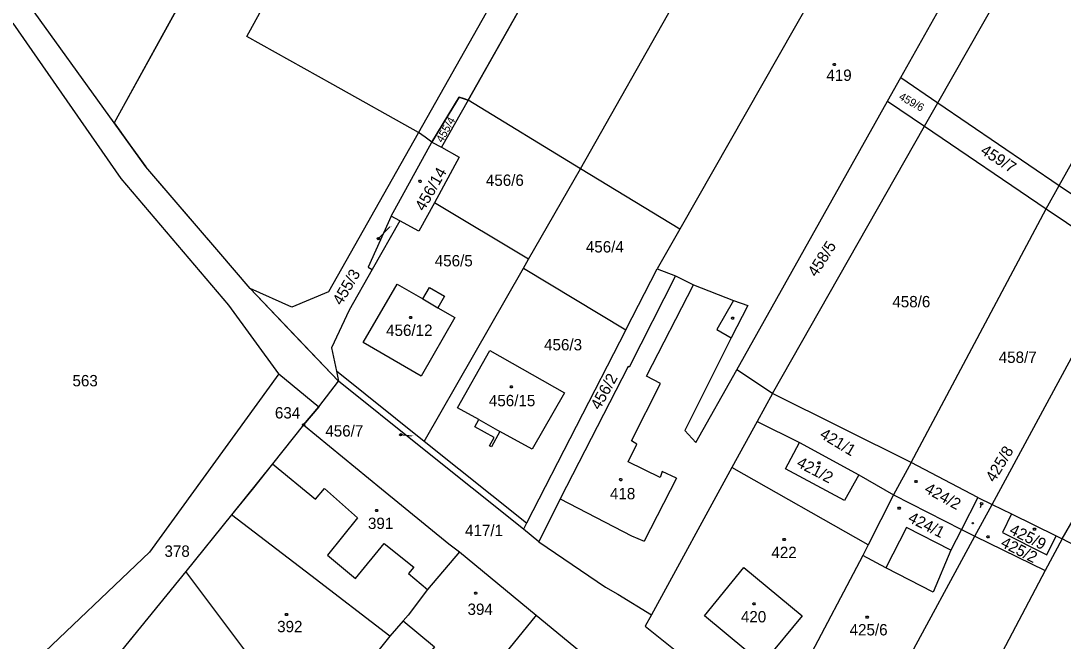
# Model space of a CAD drawing. Extents: x -634640 to -629202, y -1196156 to -1190068.
# Drawn here: x -631895.1 to -631739, y -1192341.9 to -1192249 of the extents above; entities that cross this region are included whole.
import ezdxf

# ---------------------------------------------------------------- set-up
doc = ezdxf.new("R2010")
doc.units = 0
for name, color, linetype in [('Obvod převzatý', 7, 'Continuous'), ('Obvod šetřený', 7, 'Continuous'), ('Vrstva 1', 7, 'Continuous'), ('Vrstva 2', 7, 'Continuous'), ('Vrstva 3', 7, 'Continuous'), ('Vrstva 4', 7, 'Continuous'), ('Vrstva 5', 7, 'Continuous'), ('Vrstva 7', 7, 'Continuous'), ('Vrstva 8', 7, 'Continuous')]:
    doc.layers.add(name, color=color, linetype=linetype)

msp = doc.modelspace()

# ---------------------------------------------------------------- linework, layer by layer
at = {"layer": 'Obvod převzatý'}
for points in [[(-631828.14, -1192260.86), (-631828.805, -1192260.62), (-631829.47, -1192260.38), (-631831.52, -1192263.755), (-631833.57, -1192267.13), (-631834.565, -1192266.415), (-631835.56, -1192265.7), (-631848.41, -1192258.505), (-631861.26, -1192251.31), (-631858.765, -1192246.78), (-631856.27, -1192242.25), (-631860.915, -1192239.685), (-631866.088, -1192236.828), (-631873.777, -1192250.837), (-631881.15, -1192264.27), (-631878.79, -1192267.545), (-631876.43, -1192270.82)], [(-631847.57, -1192302.96), (-631854.17, -1192296.005), (-631860.77, -1192289.05), (-631865.5, -1192283.55), (-631870.965, -1192277.185), (-631876.43, -1192270.82)], [(-631852.78, -1192309.47), (-631850.5, -1192306.81), (-631847.57, -1192302.96)], [(-631852.78, -1192309.47), (-631857.43, -1192315.35), (-631860.495, -1192319.155), (-631863.56, -1192322.96), (-631870.4, -1192331.45), (-631881.165, -1192344.625), (-631891.93, -1192357.8)]]:
    msp.add_lwpolyline(points, dxfattribs=at)
at = {"layer": 'Obvod šetřený'}
msp.add_lwpolyline([(-631828.14, -1192260.86), (-631770.72, -1192159.345), (-631713.3, -1192057.83), (-631710.55, -1192057.545), (-631707.8, -1192057.26), (-631694.81, -1192065.06), (-631675.8, -1192076.49), (-631658.57, -1192086.85), (-631641.27, -1192097.24), (-631633.835, -1192101.715), (-631626.4, -1192106.19), (-631621.345, -1192109.22), (-631616.29, -1192112.25), (-631611.64, -1192115.048), (-631606.99, -1192117.845), (-631603.89, -1192119.71), (-631598.89, -1192123.93), (-631590.975, -1192122.16)], dxfattribs=at)
at = {"layer": 'Vrstva 1'}
for p, q in [((-631713.3, -1192057.83), (-631828.14, -1192260.86)), ((-631811.29, -1192271.13), (-631694.81, -1192065.06)), ((-631757.75, -1192261.26), (-631658.57, -1192086.85)), ((-631881.15, -1192264.27), (-631944.14, -1192176.84)), ((-631787.54, -1192180.78), (-631849.06, -1192289.57)), ((-631739.56, -1192273.61), (-631693.54, -1192191.04)), ((-631763.12, -1192221.67), (-631796.42, -1192280.19)), ((-631763.31, -1192257.48), (-631746.9, -1192228.25)), ((-631866.403, -1192237.404), (-631881.15, -1192264.27)), ((-631880.13, -1192272.61), (-631896.29, -1192249.34)), ((-631765.27, -1192260.98), (-631763.31, -1192257.48)), ((-631763.31, -1192257.48), (-631757.75, -1192261.26)), ((-631833.57, -1192267.13), (-631829.47, -1192260.38)), ((-631828.14, -1192260.86), (-631832.13, -1192267.91)), ((-631829.47, -1192260.38), (-631828.14, -1192260.86)), ((-631811.29, -1192271.13), (-631828.14, -1192260.86)), ((-631787.88, -1192301.25), (-631765.27, -1192260.98)), ((-631765.27, -1192260.98), (-631759.73, -1192264.74)), ((-631759.73, -1192264.74), (-631757.75, -1192261.26)), ((-631757.75, -1192261.26), (-631739.56, -1192273.61)), ((-631876.43, -1192270.82), (-631881.15, -1192264.27)), ((-631782.51, -1192304.79), (-631759.73, -1192264.74)), ((-631759.73, -1192264.74), (-631741.52, -1192277.11)), ((-631839.63, -1192278.23), (-631833.57, -1192267.13)), ((-631833.57, -1192267.13), (-631832.13, -1192267.91)), ((-631829.45, -1192269.37), (-631833.18, -1192276.23)), ((-631832.13, -1192267.91), (-631829.45, -1192269.37)), ((-631865.5, -1192283.55), (-631876.43, -1192270.82)), ((-631819.08, -1192284.69), (-631811.29, -1192271.13)), ((-631796.42, -1192280.19), (-631811.29, -1192271.13)), ((-631863.97, -1192291.54), (-631880.13, -1192272.61)), ((-631741.52, -1192277.11), (-631739.56, -1192273.61)), ((-631739.56, -1192273.61), (-631728, -1192281.47)), ((-631833.18, -1192276.23), (-631835.51, -1192280.5)), ((-631819.08, -1192284.69), (-631833.18, -1192276.23)), ((-631761.74, -1192315.12), (-631741.52, -1192277.11)), ((-631741.52, -1192277.11), (-631729.91, -1192285)), ((-631839.63, -1192278.23), (-631843.1, -1192285.89)), ((-631838.36, -1192278.93), (-631839.63, -1192278.23)), ((-631838.36, -1192278.93), (-631842.5, -1192286.24)), ((-631835.51, -1192280.5), (-631838.36, -1192278.93)), ((-631796.42, -1192280.19), (-631799.78, -1192286.1)), ((-631860.77, -1192289.05), (-631865.5, -1192283.55)), ((-631819.85, -1192286.04), (-631819.08, -1192284.69)), ((-631749.63, -1192321.4), (-631729.91, -1192285)), ((-631842.5, -1192286.24), (-631845.93, -1192292.3)), ((-631843.1, -1192285.89), (-631842.5, -1192286.24)), ((-631834.72, -1192311.97), (-631819.85, -1192286.04)), ((-631819.85, -1192286.04), (-631804.48, -1192295.24)), ((-631804.48, -1192295.24), (-631799.78, -1192286.1)), ((-631799.78, -1192286.1), (-631797.04, -1192287.17)), ((-631797.04, -1192287.17), (-631803.97, -1192300.84)), ((-631797.04, -1192287.17), (-631794.35, -1192288.51)), ((-631854.54, -1192291.88), (-631860.77, -1192289.05)), ((-631847.57, -1192302.96), (-631860.77, -1192289.05)), ((-631849.06, -1192289.57), (-631854.54, -1192291.88)), ((-631843.86, -1192297.16), (-631838.77, -1192288.4)), ((-631838.77, -1192288.4), (-631834.91, -1192290.62)), ((-631834.91, -1192290.62), (-631833.93, -1192288.9)), ((-631833.93, -1192288.9), (-631831.65, -1192290.21)), ((-631794.35, -1192288.51), (-631788.38, -1192290.84)), ((-631831.65, -1192290.21), (-631832.66, -1192291.96)), ((-631788.38, -1192290.84), (-631786.21, -1192291.59)), ((-631856.48, -1192301.87), (-631863.97, -1192291.54)), ((-631845.93, -1192292.3), (-631848.57, -1192297.95)), ((-631832.66, -1192291.96), (-631830.1, -1192293.43)), ((-631786.21, -1192291.59), (-631788.73, -1192296.44)), ((-631739.13, -1192326.55), (-631719.28, -1192292.22)), ((-631830.1, -1192293.43), (-631835.15, -1192302.2)), ((-631804.48, -1192295.24), (-631819.39, -1192324.23)), ((-631835.15, -1192302.2), (-631843.86, -1192297.16)), ((-631788.73, -1192296.44), (-631795.67, -1192310.34)), ((-631848.57, -1192297.95), (-631847.87, -1192301.46)), ((-631829.73, -1192306.93), (-631824.87, -1192298.35)), ((-631824.87, -1192298.35), (-631813.68, -1192304.69)), ((-631856.48, -1192301.87), (-631875.84, -1192328.57)), ((-631856.48, -1192301.87), (-631850.5, -1192306.81)), ((-631834.72, -1192311.97), (-631847.87, -1192301.46)), ((-631847.87, -1192301.46), (-631847.57, -1192302.96)), ((-631804.15, -1192300.77), (-631814.31, -1192320.55)), ((-631803.97, -1192300.84), (-631804.15, -1192300.77)), ((-631793.99, -1192312.11), (-631787.88, -1192301.25)), ((-631782.51, -1192304.79), (-631787.88, -1192301.25)), ((-631835.22, -1192312.84), (-631847.57, -1192302.96)), ((-631813.68, -1192304.69), (-631818.55, -1192313.15)), ((-631782.51, -1192304.79), (-631784.81, -1192308.99)), ((-631761.74, -1192315.12), (-631782.51, -1192304.79)), ((-631850.5, -1192306.81), (-631852.78, -1192309.47)), ((-631826.53, -1192308.68), (-631829.73, -1192306.93)), ((-631852.78, -1192309.47), (-631857.43, -1192315.35)), ((-631852.78, -1192309.47), (-631841.11, -1192319.08)), ((-631827.12, -1192309.77), (-631826.53, -1192308.68)), ((-631824.22, -1192311.36), (-631827.12, -1192309.77)), ((-631784.81, -1192308.99), (-631788.59, -1192315.9)), ((-631784.81, -1192308.99), (-631778.45, -1192312.11)), ((-631824.92, -1192312.63), (-631824.22, -1192311.36)), ((-631823.38, -1192310.5), (-631824.63, -1192312.79)), ((-631818.55, -1192313.15), (-631823.38, -1192310.5)), ((-631795.67, -1192310.34), (-631793.99, -1192312.11)), ((-631819.85, -1192325.12), (-631835.22, -1192312.84)), ((-631819.39, -1192324.23), (-631834.72, -1192311.97)), ((-631824.63, -1192312.79), (-631824.92, -1192312.63)), ((-631778.45, -1192312.11), (-631769.57, -1192316.97)), ((-631857.43, -1192315.35), (-631863.56, -1192322.96)), ((-631788.59, -1192315.9), (-631800.66, -1192337.95)), ((-631768.17, -1192327.46), (-631788.59, -1192315.9)), ((-631761.74, -1192315.12), (-631764.41, -1192319.96)), ((-631751.74, -1192320.37), (-631761.74, -1192315.12)), ((-631769.57, -1192316.97), (-631764.41, -1192319.96)), ((-631841.11, -1192319.08), (-631831.02, -1192327.29)), ((-631814.31, -1192320.55), (-631817.51, -1192326.99)), ((-631764.41, -1192319.96), (-631768.17, -1192327.46)), ((-631764.41, -1192319.96), (-631754.22, -1192325.15)), ((-631751.74, -1192320.37), (-631754.22, -1192325.15)), ((-631751.74, -1192320.37), (-631749.63, -1192321.4)), ((-631752.2, -1192326.14), (-631749.63, -1192321.4)), ((-631749.63, -1192321.4), (-631746.69, -1192322.84)), ((-631863.56, -1192322.96), (-631870.4, -1192331.45)), ((-631851.67, -1192332.08), (-631863.56, -1192322.96)), ((-631746.69, -1192322.84), (-631748.08, -1192325.63)), ((-631746.69, -1192322.84), (-631740.03, -1192326.11)), ((-631819.39, -1192324.23), (-631819.85, -1192325.12)), ((-631817.51, -1192326.99), (-631819.85, -1192325.12)), ((-631754.22, -1192325.15), (-631755.82, -1192328.27)), ((-631754.22, -1192325.15), (-631752.2, -1192326.14)), ((-631817.51, -1192326.99), (-631807.54, -1192333.79)), ((-631764.26, -1192348.42), (-631752.2, -1192326.14)), ((-631752.2, -1192326.14), (-631741.66, -1192331.32)), ((-631748.08, -1192325.63), (-631741.44, -1192328.95)), ((-631739.13, -1192326.55), (-631741.66, -1192331.32)), ((-631741.44, -1192328.95), (-631740.03, -1192326.11)), ((-631740.03, -1192326.11), (-631739.13, -1192326.55)), ((-631721.73, -1192335.89), (-631739.13, -1192326.55)), ((-631875.84, -1192328.57), (-631900.25, -1192351.76)), ((-631829.42, -1192328.51), (-631834.19, -1192334.13)), ((-631831.02, -1192327.29), (-631829.42, -1192328.51)), ((-631829.42, -1192328.51), (-631817.92, -1192338.02)), ((-631768.17, -1192327.46), (-631768.96, -1192329.04)), ((-631755.82, -1192328.27), (-631758.45, -1192334.54)), ((-631768.96, -1192329.04), (-631781.21, -1192352.21)), ((-631765.52, -1192330.91), (-631768.96, -1192329.04)), ((-631870.4, -1192331.45), (-631891.93, -1192357.8)), ((-631851.91, -1192356.15), (-631870.4, -1192331.45)), ((-631792.72, -1192338.1), (-631786.79, -1192330.85)), ((-631786.79, -1192330.85), (-631778.05, -1192338.09)), ((-631758.45, -1192334.54), (-631765.52, -1192330.91)), ((-631741.66, -1192331.32), (-631755.6, -1192357.68)), ((-631839.86, -1192341.15), (-631851.67, -1192332.08)), ((-631834.19, -1192334.13), (-631837.09, -1192337.98)), ((-631807.54, -1192333.79), (-631805.69, -1192334.85)), ((-631805.69, -1192334.85), (-631800.66, -1192337.95)), ((-631837.09, -1192337.98), (-631837.84, -1192338.84)), ((-631817.92, -1192338.02), (-631825.64, -1192347.45)), ((-631817.92, -1192338.02), (-631805.35, -1192348.31)), ((-631800.66, -1192337.95), (-631801.6, -1192339.67)), ((-631786.5, -1192343.23), (-631792.72, -1192338.1)), ((-631778.05, -1192338.09), (-631783.6, -1192344.79)), ((-631837.84, -1192338.84), (-631839.86, -1192341.15)), ((-631801.6, -1192339.67), (-631782.54, -1192354.73)), ((-631839.86, -1192341.15), (-631845.68, -1192348.4))]:
    msp.add_line(p, q, dxfattribs=at)
at = {"layer": 'Vrstva 3'}
for points in [[(-631773.18, -1192255.37), (-631773.09, -1192255.52), (-631773.18, -1192255.67), (-631773.36, -1192255.67), (-631773.45, -1192255.52), (-631773.36, -1192255.37), (-631773.18, -1192255.37)], [(-631752.44, -1192324.1), (-631752.379, -1192324.2), (-631752.44, -1192324.3), (-631752.56, -1192324.3), (-631752.621, -1192324.2), (-631752.56, -1192324.1), (-631752.44, -1192324.1)], [(-631780.68, -1192326.49), (-631780.59, -1192326.64), (-631780.68, -1192326.79), (-631780.86, -1192326.79), (-631780.95, -1192326.64), (-631780.86, -1192326.49), (-631780.68, -1192326.49)], [(-631750.16, -1192326.1), (-631750.07, -1192326.25), (-631750.16, -1192326.4), (-631750.34, -1192326.4), (-631750.43, -1192326.25), (-631750.34, -1192326.1), (-631750.16, -1192326.1)], [(-631855.25, -1192337.74), (-631855.16, -1192337.89), (-631855.25, -1192338.04), (-631855.43, -1192338.04), (-631855.52, -1192337.89), (-631855.43, -1192337.74), (-631855.25, -1192337.74)], [(-631768.24, -1192338.16), (-631768.15, -1192338.31), (-631768.24, -1192338.46), (-631768.42, -1192338.46), (-631768.51, -1192338.31), (-631768.42, -1192338.16), (-631768.24, -1192338.16)]]:
    msp.add_lwpolyline(points, dxfattribs=at)
at = {"layer": 'Vrstva 4'}
for p, q in [((-631801.42, -1192302.18), (-631794.35, -1192288.51)), ((-631834.91, -1192290.62), (-631832.66, -1192291.96)), ((-631788.38, -1192290.84), (-631790.87, -1192295.22)), ((-631790.87, -1192295.22), (-631788.73, -1192296.44)), ((-631799.31, -1192303.27), (-631801.42, -1192302.18)), ((-631803.66, -1192311.89), (-631799.31, -1192303.27)), ((-631826.53, -1192308.68), (-631823.38, -1192310.5)), ((-631804.15, -1192315.02), (-631802.84, -1192312.39)), ((-631802.84, -1192312.39), (-631803.66, -1192311.89)), ((-631780.57, -1192316.1), (-631778.45, -1192312.11)), ((-631857.43, -1192315.35), (-631850.99, -1192320.63)), ((-631799.37, -1192317.37), (-631804.15, -1192315.02)), ((-631771.72, -1192320.82), (-631780.57, -1192316.1)), ((-631796.89, -1192317.48), (-631801.73, -1192326.93)), ((-631799.06, -1192316.47), (-631799.37, -1192317.37)), ((-631796.89, -1192317.48), (-631799.06, -1192316.47)), ((-631769.57, -1192316.97), (-631771.72, -1192320.82)), ((-631850.99, -1192320.63), (-631849.66, -1192319.04)), ((-631849.66, -1192319.04), (-631844.69, -1192323.41)), ((-631814.31, -1192320.55), (-631803.63, -1192326.1)), ((-631844.69, -1192323.41), (-631849.21, -1192329.03)), ((-631762.44, -1192324.89), (-631765.52, -1192330.91)), ((-631755.82, -1192328.27), (-631762.44, -1192324.89)), ((-631803.63, -1192326.1), (-631801.73, -1192326.93)), ((-631845.01, -1192332.52), (-631840.7, -1192327.26)), ((-631840.7, -1192327.26), (-631836.25, -1192330.8)), ((-631849.21, -1192329.03), (-631845.01, -1192332.52)), ((-631836.25, -1192330.8), (-631837.07, -1192331.76)), ((-631837.07, -1192331.76), (-631834.19, -1192334.13))]:
    msp.add_line(p, q, dxfattribs=at)
msp.add_lwpolyline([(-631837.84, -1192338.84), (-631833.18, -1192342.75), (-631833.85, -1192343.6), (-631830.54, -1192346.35), (-631829.8, -1192345.43), (-631826.35, -1192348.31)], dxfattribs=at)
at = {"layer": 'Vrstva 5'}
for points in [[(-631835.23, -1192272.86), (-631835.14, -1192273.01), (-631835.23, -1192273.16), (-631835.41, -1192273.16), (-631835.5, -1192273.01), (-631835.41, -1192272.86), (-631835.23, -1192272.86)], [(-631836.64, -1192293.26), (-631836.55, -1192293.41), (-631836.64, -1192293.56), (-631836.82, -1192293.56), (-631836.91, -1192293.41), (-631836.82, -1192293.26), (-631836.64, -1192293.26)], [(-631788.41, -1192293.36), (-631788.32, -1192293.51), (-631788.41, -1192293.66), (-631788.59, -1192293.66), (-631788.68, -1192293.51), (-631788.59, -1192293.36), (-631788.41, -1192293.36)], [(-631821.55, -1192303.64), (-631821.46, -1192303.79), (-631821.55, -1192303.94), (-631821.73, -1192303.94), (-631821.82, -1192303.79), (-631821.73, -1192303.64), (-631821.55, -1192303.64)], [(-631775.48, -1192315.04), (-631775.39, -1192315.19), (-631775.48, -1192315.34), (-631775.66, -1192315.34), (-631775.75, -1192315.19), (-631775.66, -1192315.04), (-631775.48, -1192315.04)], [(-631805.16, -1192317.55), (-631805.07, -1192317.7), (-631805.16, -1192317.85), (-631805.34, -1192317.85), (-631805.43, -1192317.7), (-631805.34, -1192317.55), (-631805.16, -1192317.55)], [(-631760.93, -1192317.81), (-631760.84, -1192317.96), (-631760.93, -1192318.11), (-631761.11, -1192318.11), (-631761.2, -1192317.96), (-631761.11, -1192317.81), (-631760.93, -1192317.81)], [(-631841.73, -1192322.19), (-631841.64, -1192322.34), (-631841.73, -1192322.49), (-631841.91, -1192322.49), (-631842, -1192322.34), (-631841.91, -1192322.19), (-631841.73, -1192322.19)], [(-631763.45, -1192321.81), (-631763.36, -1192321.96), (-631763.45, -1192322.11), (-631763.63, -1192322.11), (-631763.72, -1192321.96), (-631763.63, -1192321.81), (-631763.45, -1192321.81)], [(-631743.17, -1192324.96), (-631743.08, -1192325.11), (-631743.17, -1192325.26), (-631743.35, -1192325.26), (-631743.44, -1192325.11), (-631743.35, -1192324.96), (-631743.17, -1192324.96)], [(-631826.89, -1192334.57), (-631826.8, -1192334.72), (-631826.89, -1192334.87), (-631827.07, -1192334.87), (-631827.16, -1192334.72), (-631827.07, -1192334.57), (-631826.89, -1192334.57)], [(-631785.22, -1192336.17), (-631785.13, -1192336.32), (-631785.22, -1192336.47), (-631785.4, -1192336.47), (-631785.49, -1192336.32), (-631785.4, -1192336.17), (-631785.22, -1192336.17)]]:
    msp.add_lwpolyline(points, dxfattribs=at)
at = {"layer": 'Vrstva 7'}
for p, q in [((-631839.85, -1192279.83), (-631841.58, -1192281.6)), ((-631836.59, -1192311.16), (-631838.24, -1192310.97)), ((-631751.36, -1192321.85), (-631751.2, -1192321.3))]:
    msp.add_line(p, q, dxfattribs=at)
for points in [[(-631841.749, -1192281.644), (-631841.709, -1192281.474), (-631841.539, -1192281.43), (-631841.411, -1192281.556), (-631841.451, -1192281.726), (-631841.621, -1192281.77), (-631841.749, -1192281.644)], [(-631838.379, -1192310.864), (-631838.22, -1192310.791), (-631838.081, -1192310.898), (-631838.101, -1192311.076), (-631838.26, -1192311.149), (-631838.399, -1192311.042), (-631838.379, -1192310.864)], [(-631751.073, -1192321.18), (-631751.027, -1192321.349), (-631751.154, -1192321.469), (-631751.327, -1192321.42), (-631751.373, -1192321.251), (-631751.246, -1192321.131), (-631751.073, -1192321.18)]]:
    msp.add_lwpolyline(points, dxfattribs=at)
at = {"layer": 'Vrstva 8'}
msp.add_lwpolyline([(-631852.69, -1192309.32), (-631852.6, -1192309.47), (-631852.69, -1192309.62), (-631852.87, -1192309.62), (-631852.96, -1192309.47), (-631852.87, -1192309.32), (-631852.69, -1192309.32)], dxfattribs=at)

# ---------------------------------------------------------------- texts
at = {"layer": 'Vrstva 2'}
for s, height, p in [('419', 1.7, (-631774.453, -1192257.96)), ('456/6', 1.7, (-631825.463, -1192273.69)), ('455/3', 0.1, (-631839.836, -1192279.83)), ('456/4', 1.7, (-631810.483, -1192283.67)), ('456/5', 1.7, (-631833.123, -1192285.75)), ('458/6', 1.7, (-631764.563, -1192291.88)), ('456/12', 1.7, (-631840.413, -1192296.17)), ('456/3', 1.7, (-631816.743, -1192298.33)), ('458/7', 1.7, (-631748.623, -1192300.21)), ('563', 1.7, (-631887.403, -1192303.72)), ('456/15', 1.7, (-631825.013, -1192306.7)), ('456/7', 0.1, (-631836.576, -1192311.16)), ('418', 1.7, (-631806.873, -1192320.64)), ('391', 1.7, (-631843.133, -1192325.09)), ('417/1', 1.7, (-631828.583, -1192326.15)), ('378', 1.7, (-631873.623, -1192329.26)), ('422', 1.7, (-631782.683, -1192329.45)), ('394', 1.7, (-631828.213, -1192337.96)), ('420', 1.7, (-631787.253, -1192339.08)), ('392', 1.7, (-631856.733, -1192340.55)), ('425/6', 1.7, (-631770.963, -1192341.03))]:
    msp.add_text(s, height=height, dxfattribs=at).set_placement(p)
for s, height, rotation, p in [('459/6', 1.19, 330.76854, (-631763.705, -1192260.661)), ('455/4', 1.2, 60.56164, (-631831.978, -1192267.314)), ('459/7', 1.7, 327.1589, (-631751.491, -1192268.779)), ('456/14', 1.7, 60.16057, (-631834.732, -1192277.594)), ('458/5', 1.7, 57.35308, (-631775.962, -1192287.45)), ('456/2', 1.7, 60.84812, (-631808.424, -1192307.373)), ('421/1', 1.7, 329.10696, (-631775.576, -1192311.322)), ('421/2', 1.7, 332.20093, (-631779.04, -1192315.661)), ('424/2', 1.7, 331.11231, (-631759.882, -1192319.535)), ('425/8', 0.1, 64.45775, (-631751.354, -1192321.837)), ('424/1', 1.7, 333.28955, (-631762.348, -1192323.937)), ('425/9', 1.7, 333.9198, (-631747.167, -1192325.764)), ('425/2', 1.7, 333.06037, (-631748.468, -1192327.658))]:
    msp.add_text(s, height=height, rotation=rotation, dxfattribs=at).set_placement(p)
at = {"layer": 'Vrstva 7'}
for s, rotation, p in [('455/3', 59.47302, (-631847.098, -1192291.711)), ('425/8', 59.07195, (-631749.258, -1192318.206))]:
    msp.add_text(s, height=1.7, rotation=rotation, dxfattribs=at).set_placement(p)
msp.add_text('456/7', height=1.7, dxfattribs=at).set_placement((-631849.518, -1192311.24))
at = {"layer": 'Vrstva 8'}
msp.add_text('634', height=1.7, dxfattribs=at).set_placement((-631857.073, -1192308.54))

doc.saveas('drawing.dxf')
